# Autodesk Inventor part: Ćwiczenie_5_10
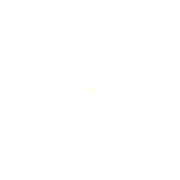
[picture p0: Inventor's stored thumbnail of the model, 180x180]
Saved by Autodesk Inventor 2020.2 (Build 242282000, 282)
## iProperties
Created: 2005-02
Part Number: Ćwiczenie_5_10
Document SubType Name: Modeling
Designer: F.Stasiak
Manufacturer: Standard
Standards Organization: Custom
Density: 1 g/cm^3
Material: Ogólny
Appearance: Domyślna
Manager: www.cadconsulting.pl
Company: Fabian Stasiak CAD Consulting
Author: F.Stasiak
Subject: Zbiór ćwiczeń. Autodesk Inventor 2020. Kurs podstawowy
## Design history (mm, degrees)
sketch "Silnik z boku"
  geometry: 1 further point
  constraints: 1 other
sketch "Silnik z przodu"
  geometry: 1 further point
  constraints: 1 other
node "Korpusy bryłowe"
node "Korpusy powierzchniowe"
